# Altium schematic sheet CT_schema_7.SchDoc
size 252 x 159 mm
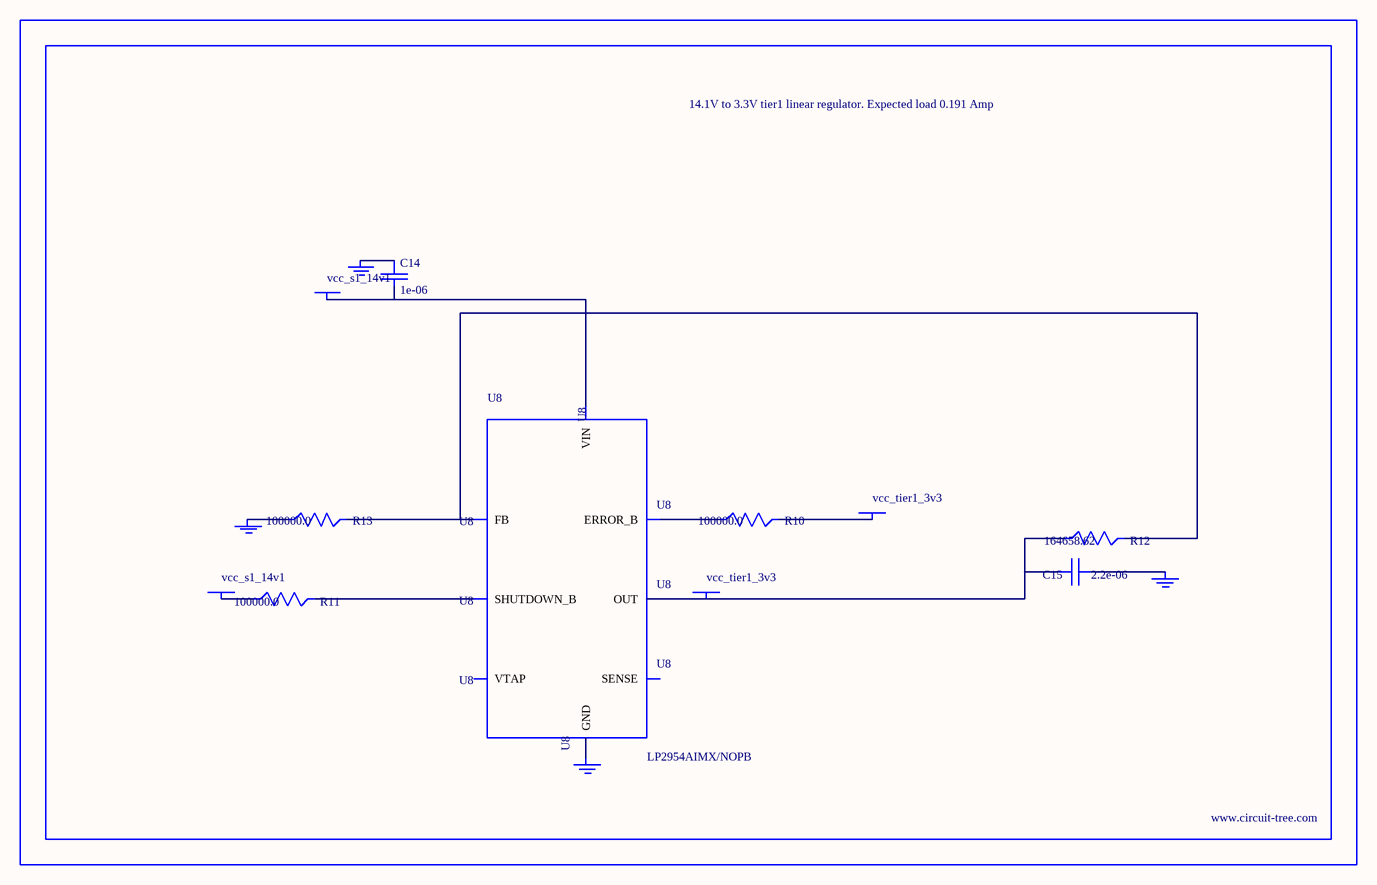
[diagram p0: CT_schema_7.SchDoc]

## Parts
BORDER6  (no value)
C14  1e-06  [EXV-9B]
C15  2.2e-06  [EXV-9B]
GND_INSTANCE_6_0  (no value)
GND_INSTANCE_6_1  (no value)
GND_INSTANCE_6_2  (no value)
GND_INSTANCE_6_3  (no value)
POWER_INSTANCE_6_0  vcc_s1_14v1
POWER_INSTANCE_6_1  vcc_tier1_3v3
POWER_INSTANCE_6_2  vcc_s1_14v1
POWER_INSTANCE_6_3  vcc_tier1_3v3
R10  100000.0  [R0603]
R11  100000.0  [R0603]
R12  164658.62  [R0603]
R13  100000.0  [R0603]
U8  LP2954AIMX/NOPB  [LP2954]

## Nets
NetC14_1: C14.1 GND_INSTANCE_6_2.0(GND)
NetC14_2: C14.2 POWER_INSTANCE_6_2.0(PWR) U8.8(VIN)
NetC15_1: C15.1 GND_INSTANCE_6_0.0(GND)
NetC15_2: C15.2 POWER_INSTANCE_6_3.0(PWR) R12.1 U8.1(OUT)
NetGND_INSTANCE_6_1_0: GND_INSTANCE_6_1.0(GND) R13.1
NetGND_INSTANCE_6_3_0: GND_INSTANCE_6_3.0(GND) U8.4(GND)
NetPOWER_INSTANCE_6_0_0: POWER_INSTANCE_6_0.0(PWR) R11.1
NetPOWER_INSTANCE_6_1_0: POWER_INSTANCE_6_1.0(PWR) R10.2
NetR10_1: R10.1 U8.5(ERROR_B)
NetR11_2: R11.2 U8.3(SHUTDOWN_B)
NetR12_2: R12.2 R13.2 U8.7(FB)

Not connected (* = marked no-connect by the designer): U8 2(SENSE) 6(VTAP)

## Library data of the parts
BORDER6 = BORDER_PAGE6
C14 = EDK105M050A9BAA
C15 = EDK225M050A9BAA
GND_INSTANCE_6_0-GND_INSTANCE_6_3 = GND
POWER_INSTANCE_6_0-POWER_INSTANCE_6_3 = PWR
R10 R11 R13 = RC0603JR-07100KL
R12 = R12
